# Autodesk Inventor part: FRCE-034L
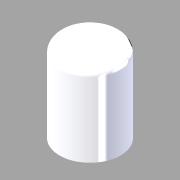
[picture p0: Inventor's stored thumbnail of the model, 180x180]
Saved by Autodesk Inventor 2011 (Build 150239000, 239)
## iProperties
Created: 2011-03
Part Number: FRCE-034L
Document SubType Name: Modeling
Designer: tananaev
Density: 1 g/cm^3
Mass: 977.758 g
Surface Area: 618.216 cm^2
Volume: 977.758 cm^3
Author: tananaev
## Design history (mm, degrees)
sketch "Эскиз1"
  geometry: C1 r 66 at (0, 0); 1 further point
  constraints: 1 centre point, 1 coincident
  dimensions: "d0" = 132 diameter of C1
extrude "Выдавливание1" new body sketch "Эскиз1" distance "d1" = 180; taper "d2" = 0 deg
fillet "Сопряжение1" dims "d3" = 20
sketch "Эскиз2"
  geometry: C1 r 66 at (0, 0) reference; C2 r 36 at (0, 0); C3 r 31.5 at (0, 0); C4 r 66 at (0, 0) reference; C5 r 45 at (0, 0)
  constraints: 3 centre point, 3 coincident
  dimensions: "d4" = 72 diameter of C2; "d5" = 63 diameter of C3; "d8" = 90 diameter of C5
extrude "Выдавливание3" cut sketch "Эскиз2" distance "d9" = 6; taper "d10" = 0 deg
hole "Отверстие1" diameter "d13" = 38.952; stored, may be unused: countersink angle "d17" = 90 deg, drill point angle "d19" = 118 deg; dims "d11" = 10, "d12" = 10, "d14" = 6, "d15" = 4, "d16" = 2, "d18" = 20
node "Твердое тело1"
